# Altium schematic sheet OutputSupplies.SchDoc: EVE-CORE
size A4; Organization: Ingenia Motion Control; Address1: Carrer Avila, 124, 2B; Address2: 08018 Barcelona Spain; Address3: www.ingeniamc.com; Address4: www.ingeniamc.com; Documentation: https://doc.ingeniamc.com/x/coAZBg
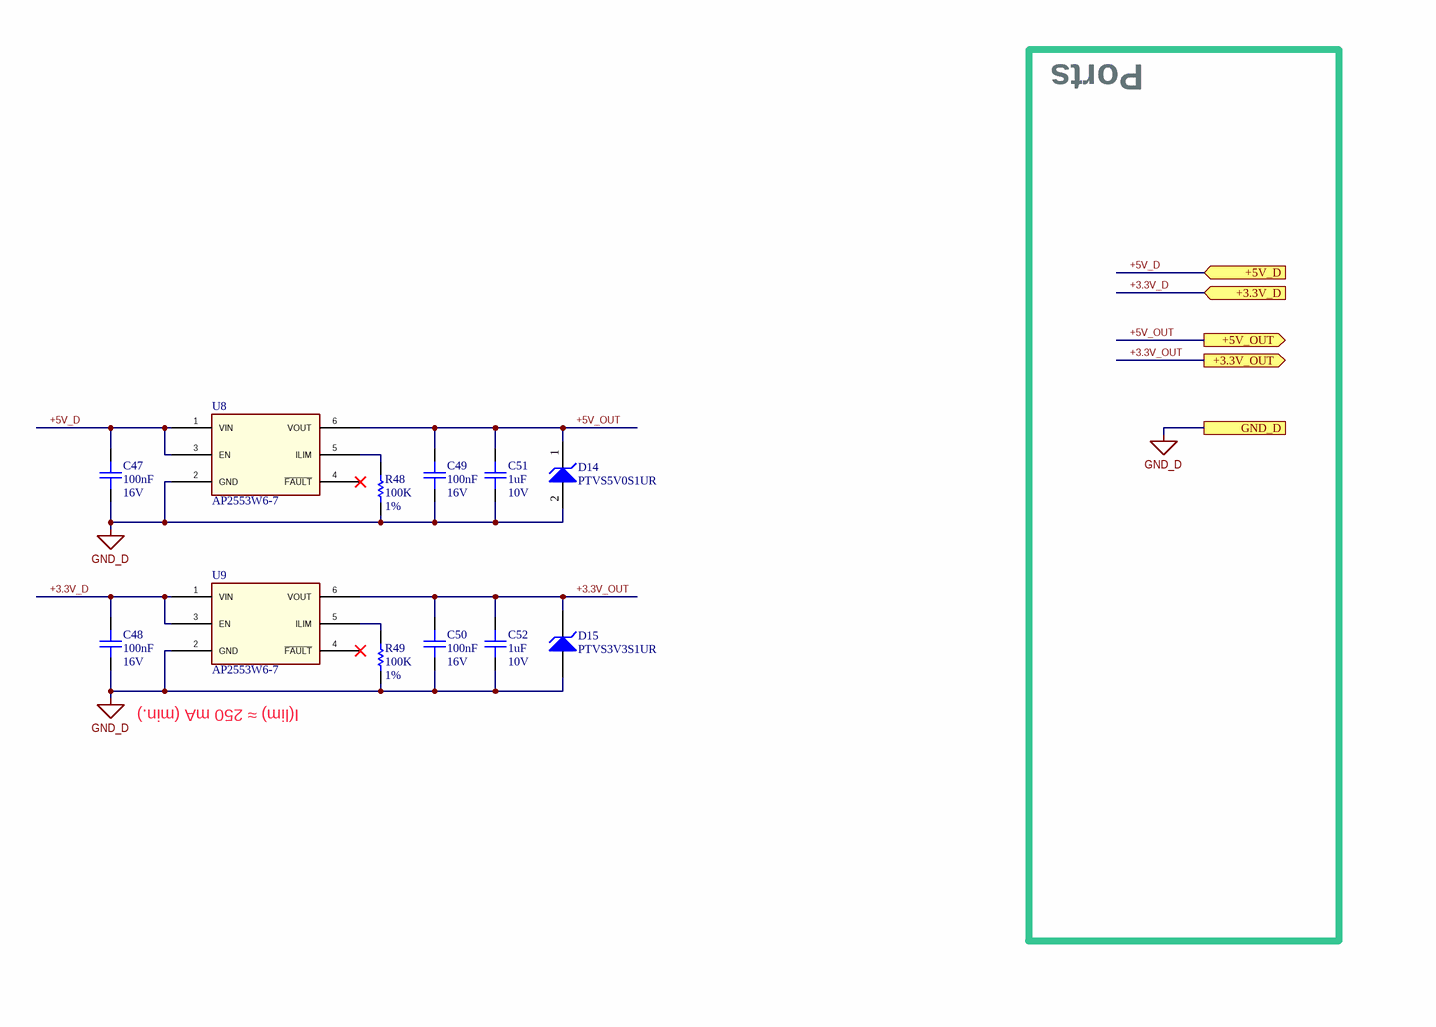
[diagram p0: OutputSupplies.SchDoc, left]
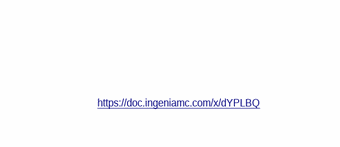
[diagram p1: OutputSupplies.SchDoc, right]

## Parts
C47  value 100nF  Voltage: 16V  [C_0402]  (hidden comment: C_0402--100nF--16V)
C48  value 100nF  Voltage: 16V  [C_0402]  (hidden comment: C_0402--100nF--16V)
C49  value 100nF  Voltage: 16V  [C_0402]  (hidden comment: C_0402--100nF--16V)
C50  value 100nF  Voltage: 16V  [C_0402]  (hidden comment: C_0402--100nF--16V)
C51  value 1uF  Voltage: 10V  [C_0402]  (hidden comment: C_0402--1uF--10V)
C52  value 1uF  Voltage: 10V  [C_0402]  (hidden comment: C_0402--1uF--10V)
D14  Part Number: PTVS5V0S1UR  [SOD123W2]  (hidden comment: TVS2)
D15  PTVS3V3S1UR  [SOD123W]
R48  value 100K  Tolerance: 1%  [R_0402]  (hidden comment: R_0402--100K--1%)
R49  value 100K  Tolerance: 1%  [R_0402]  (hidden comment: R_0402--100K--1%)
U8  AP2553W6-7  [SOT23-6N]
U9  AP2553W6-7  [SOT23-6N]

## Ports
+3.3V_D (in), +3.3V_OUT (out), +5V_D (in), +5V_OUT (out), GND_D

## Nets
GND_D: C47.2 C48.2 C49.2 C50.2 C51.2 C52.2 D14.2(A) D15.1(A) R48.2 R49.2 U8.2(GND) U9.2(GND) ; port GND_D
+3.3V_D: C48.1 U9.1(VIN) U9.3(EN) ; port +3.3V_D
+3.3V_OUT: C50.1 C52.1 D15.2(K) U9.6(VOUT) ; port +3.3V_OUT
+5V_D: C47.1 U8.1(VIN) U8.3(EN) ; port +5V_D
+5V_OUT: C49.1 C51.1 D14.1(K) U8.6(VOUT) ; port +5V_OUT
NetR48_1: R48.1 U8.5(ILIM)
NetR49_1: R49.1 U9.5(ILIM)

Not connected (* = marked no-connect by the designer): U8 4(~{FAULT})*; U9 4(~{FAULT})*

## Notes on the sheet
- Ports
- I(lim) ≈ 250 mA (min.)
- https://doc.ingeniamc.com/x/dYPLBQ

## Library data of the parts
C47-C50 = C_0402[[/\]]100nF[[/\]]16V: CAP CER 100nF 16V X7R 0402; ManufacturerName: Murata; ManufacturerPN: GRM155R71C104KA88D; AlternativeManufacturer: Wurth; IsPreferred: 1; IngeniaID: 672; InternalStock: 0; TemperatureMaxC: 125; TemperatureMinC: -55; MTBF55h: 36129613; AlternativePN: 885012205037
C51 C52 = C_0402[[/\]]1uF[[/\]]10V: Capacitor 1uF 10V Ceramic X7S 0402; ManufacturerName: TDK Corporation; ManufacturerPN: C1005X7S1A105K050BC; AlternativeManufacturer: Murata; IsPreferred: 0; IsGeneric: 1; IngeniaID: 1513; TemperatureMaxC: 125; TemperatureMinC: -55; MTBF55h: 28045508; AlternativePN: GCM155C71A105KE38D
D14 = PTVS5V0S1UR: DIODE TVS 5V, 400W, UNIDIRECTIONAL, 5%, SOD123W; ManufacturerName: NXP; ManufacturerPN: PTVS5V0S1UR,115; Value: TVS 5V; IsPreferred: 0; IngeniaID: 1306; TemperatureMaxC: 150; TemperatureMinC: -55
D15 = PTVS3V3S1UR: TVS 400W UNIDIR 3.3V; ManufacturerName: NXP; ManufacturerPN: PTVS3V3S1UR,115; Value: TVS 3.3V; IsPreferred: 0; IngeniaID: 1158
R48 R49 = R_0402[[/\]]100K[[/\]]1%: Resistor 100kohm  1/16W 1% 0402; ManufacturerName: Yageo; ManufacturerPN: RC0402FR-07100KL; AlternativeManufacturer: Bourns Inc.; IsPreferred: 0; IsGeneric: 1; IngeniaID: 1454; TemperatureMaxC: 155; TemperatureMinC: -55; MTBF55h: 83317989; AlternativePN: CR0402-FX-1003GLF
U8 U9 = AP2553W6-7: IC Load Switch Self-Protected, 5.5V Adjustable SOT23-6; ManufacturerName: Diodes Inc; IsPreferred: 0; IngeniaID: 4419; TemperatureMaxC: 125; TemperatureMinC: -40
